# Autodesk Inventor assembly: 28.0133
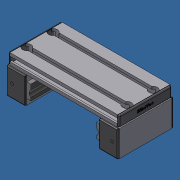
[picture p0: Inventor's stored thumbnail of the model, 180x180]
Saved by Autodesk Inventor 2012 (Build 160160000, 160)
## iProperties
Created: 2007-06
Part Number: 28.0133
Document SubType Name: Assembly
Designer: Andy Moles
Description: SLIDE LWG 32X45-90
Author: Andy Moles
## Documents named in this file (8)
- C:\Andys Backup Data\ANDY'S INVENTOR\INVENTOR LIBRARIES\PARTS LIBRARY\READY FOR USE MODULES LG\28.0133 SLIDE LWG 32X45-90.iam
- C:\Andys Backup Data\ANDY'S INVENTOR\INVENTOR LIBRARIES\PARTS LIBRARY\READY FOR USE MODULES LG\SUBCOMPONENTS\28.0126 SLIDE 45X32.ipt
- C:\Andys Backup Data\ANDY'S INVENTOR\INVENTOR LIBRARIES\PARTS LIBRARY\COMPONENTS LG\22.1094 SLIDE RAIL LG.iam
- C:\Andys Backup Data\ANDY'S INVENTOR\INVENTOR LIBRARIES\PARTS LIBRARY\FASTENING ELEMENTS\SCREWS CAP\21.1200 M8X16.ipt
- C:\Andys Backup Data\ANDY'S INVENTOR\INVENTOR LIBRARIES\PARTS LIBRARY\FASTENING ELEMENTS\NUTS\21.1351 M8 SQUARE NUT.ipt
- C:\Andys Backup Data\ANDY'S INVENTOR\INVENTOR LIBRARIES\PARTS LIBRARY\READY FOR USE MODULES LG\SUBCOMPONENTS\28.0225 SLIDE LWG 32X45-90 90X19.ipt
- C:\Andys Backup Data\ANDY'S INVENTOR\INVENTOR LIBRARIES\PARTS LIBRARY\END CAPS\22.1014_1 END CAP 90X19 GRAY.ipt
- C:\Andys Backup Data\ANDY'S INVENTOR\INVENTOR LIBRARIES\PARTS LIBRARY\END CAPS\22.1003_1 END CAP 45x32 Z Gray.iam
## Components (19 placed, 7 different names)
1. 28.0225 SLIDE LWG 32X45-90 90X19:1 — Mate:8, Flush:5, Flush:6, Insert:1, Insert:2, Insert:3, Insert:4, Mate:15, Flush:19, Mate:17, Insert:5, Insert:6, Insert:7, Insert:8, Mate:18, Flush:20, Flush:21, Mate:19, Flush:22, Flush:23
2. 28.0126 SLIDE 45X32:1 — Mate:1, Flush:1, Flush:2, Flush:3, Mate:7, Mate:8, Flush:5, Flush:6, Mate:16, Mate:20, Flush:24, Flush:25, Mate:22, Flush:28, Flush:29
3. 22.1094 SLIDE RAIL LG:1 [sub-assembly] — Mate:1, Flush:1, Mate:16
4. 28.0126 SLIDE 45X32:2 — Flush:2, Flush:3, Mate:3, Flush:4, Mate:6, Mate:7, Mate:21, Flush:26, Flush:27, Mate:23, Flush:30, Flush:31
5. 22.1094 SLIDE RAIL LG:2 [sub-assembly] — Mate:3, Flush:4, Mate:6
6. 22.1014_1 END CAP 90X19 GRAY:1 — Mate:19, Flush:22, Flush:23
7. 22.1014_1 END CAP 90X19 GRAY:2 — Mate:18, Flush:20, Flush:21
8. 21.1200 M8 x 16:1 — Insert:2
9. 21.1200 M8 x 16:2 — Insert:1
10. 21.1200 M8 x 16:3 — Insert:3
11. 21.1200 M8 x 16:4 — Insert:4
12. 21.1351 M8 SQUARE NUT:1 — Insert:5
13. 21.1351 M8 SQUARE NUT:2 — Insert:6
14. 21.1351 M8 SQUARE NUT:3 — Insert:7
15. 21.1351 M8 SQUARE NUT:4 — Insert:8
16. 22.1003_1 END CAP 45x32 Z Gray:1 [sub-assembly] — Mate:20, Flush:24, Flush:25
17. 22.1003_1 END CAP 45x32 Z Gray:2 [sub-assembly] — Mate:21, Flush:26, Flush:27
18. 22.1003_1 END CAP 45x32 Z Gray:3 [sub-assembly] — Mate:23, Flush:30, Flush:31
19. 22.1003_1 END CAP 45x32 Z Gray:4 [sub-assembly] — Mate:22, Flush:28, Flush:29
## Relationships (41: Flush 19, Mate 14, Insert 8)
- Mate:1: 28.0126 SLIDE 45X32:1 ↔ 22.1094 SLIDE RAIL LG:1
- Flush:1: 28.0126 SLIDE 45X32:1 ↔ 22.1094 SLIDE RAIL LG:1
- Flush:2: 28.0126 SLIDE 45X32:1 ↔ 28.0126 SLIDE 45X32:2
- Flush:3: 28.0126 SLIDE 45X32:1 ↔ 28.0126 SLIDE 45X32:2
- Mate:3: 28.0126 SLIDE 45X32:2 ↔ 22.1094 SLIDE RAIL LG:2
- Flush:4: 28.0126 SLIDE 45X32:2 ↔ 22.1094 SLIDE RAIL LG:2
- Mate:6: 28.0126 SLIDE 45X32:2 ↔ 22.1094 SLIDE RAIL LG:2
- Mate:7: 28.0126 SLIDE 45X32:1 ↔ 28.0126 SLIDE 45X32:2
- Mate:8: 28.0225 SLIDE LWG 32X45-90 90X19:1 ↔ 28.0126 SLIDE 45X32:1
- Flush:5: 28.0225 SLIDE LWG 32X45-90 90X19:1 ↔ 28.0126 SLIDE 45X32:1
- Flush:6: 28.0225 SLIDE LWG 32X45-90 90X19:1 ↔ 28.0126 SLIDE 45X32:1
- Insert:1: 28.0225 SLIDE LWG 32X45-90 90X19:1 ↔ 21.1200 M8 x 16:2
- Insert:2: 28.0225 SLIDE LWG 32X45-90 90X19:1 ↔ 21.1200 M8 x 16:1
- Insert:3: 28.0225 SLIDE LWG 32X45-90 90X19:1 ↔ 21.1200 M8 x 16:3
- Insert:4: 28.0225 SLIDE LWG 32X45-90 90X19:1 ↔ 21.1200 M8 x 16:4
- Mate:15: 28.0225 SLIDE LWG 32X45-90 90X19:1
- Flush:19: 28.0225 SLIDE LWG 32X45-90 90X19:1
- Mate:16: 28.0126 SLIDE 45X32:1 ↔ 22.1094 SLIDE RAIL LG:1
- Mate:17: 28.0225 SLIDE LWG 32X45-90 90X19:1
- Insert:5: 28.0225 SLIDE LWG 32X45-90 90X19:1 ↔ 21.1351 M8 SQUARE NUT:1
- Insert:6: 28.0225 SLIDE LWG 32X45-90 90X19:1 ↔ 21.1351 M8 SQUARE NUT:2
- Insert:7: 28.0225 SLIDE LWG 32X45-90 90X19:1 ↔ 21.1351 M8 SQUARE NUT:3
- Insert:8: 28.0225 SLIDE LWG 32X45-90 90X19:1 ↔ 21.1351 M8 SQUARE NUT:4
- Mate:18: 28.0225 SLIDE LWG 32X45-90 90X19:1 ↔ 22.1014_1 END CAP 90X19 GRAY:2
- Flush:20: 28.0225 SLIDE LWG 32X45-90 90X19:1 ↔ 22.1014_1 END CAP 90X19 GRAY:2
- Flush:21: 28.0225 SLIDE LWG 32X45-90 90X19:1 ↔ 22.1014_1 END CAP 90X19 GRAY:2
- Mate:19: 28.0225 SLIDE LWG 32X45-90 90X19:1 ↔ 22.1014_1 END CAP 90X19 GRAY:1
- Flush:22: 28.0225 SLIDE LWG 32X45-90 90X19:1 ↔ 22.1014_1 END CAP 90X19 GRAY:1
- Flush:23: 28.0225 SLIDE LWG 32X45-90 90X19:1 ↔ 22.1014_1 END CAP 90X19 GRAY:1
- Mate:20: 28.0126 SLIDE 45X32:1 ↔ 22.1003_1 END CAP 45x32 Z Gray:1
- Flush:24: 28.0126 SLIDE 45X32:1 ↔ 22.1003_1 END CAP 45x32 Z Gray:1
- Flush:25: 28.0126 SLIDE 45X32:1 ↔ 22.1003_1 END CAP 45x32 Z Gray:1
- Mate:21: 28.0126 SLIDE 45X32:2 ↔ 22.1003_1 END CAP 45x32 Z Gray:2
- Flush:26: 28.0126 SLIDE 45X32:2 ↔ 22.1003_1 END CAP 45x32 Z Gray:2
- Flush:27: 28.0126 SLIDE 45X32:2 ↔ 22.1003_1 END CAP 45x32 Z Gray:2
- Mate:22: 28.0126 SLIDE 45X32:1 ↔ 22.1003_1 END CAP 45x32 Z Gray:4
- Flush:28: 28.0126 SLIDE 45X32:1 ↔ 22.1003_1 END CAP 45x32 Z Gray:4
- Flush:29: 28.0126 SLIDE 45X32:1 ↔ 22.1003_1 END CAP 45x32 Z Gray:4
- Mate:23: 28.0126 SLIDE 45X32:2 ↔ 22.1003_1 END CAP 45x32 Z Gray:3
- Flush:30: 28.0126 SLIDE 45X32:2 ↔ 22.1003_1 END CAP 45x32 Z Gray:3
- Flush:31: 28.0126 SLIDE 45X32:2 ↔ 22.1003_1 END CAP 45x32 Z Gray:3
